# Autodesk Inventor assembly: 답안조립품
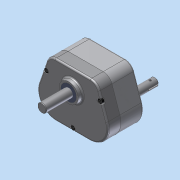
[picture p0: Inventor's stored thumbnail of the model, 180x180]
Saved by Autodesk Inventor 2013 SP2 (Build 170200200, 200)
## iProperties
Created: 2014-12
Part Number: 답안조립품
Document SubType Name: Assembly
Designer: dgall
Author: dgall
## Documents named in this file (14)
- C:\Documents and Settings\dgall\바탕 화면\441208V1037\답안조립품.iam
- C:\Documents and Settings\dgall\바탕 화면\441208V1037\본체.ipt
- C:\Documents and Settings\dgall\바탕 화면\441208V1037\커버.ipt
- C:\Documents and Settings\dgall\바탕 화면\441208V1037\메인축.ipt
- C:\Documents and Settings\dgall\바탕 화면\441208V1037\서브축.ipt
- C:\Documents and Settings\dgall\바탕 화면\441208V1037\메인기어.ipt
- C:\Documents and Settings\dgall\바탕 화면\441208V1037\서브기어.ipt
- C:\Documents and Settings\dgall\바탕 화면\441208V1037\멈춤링.ipt
- C:\Documents and Settings\dgall\바탕 화면\441208V1037\오일시일-D-15.ipt
- C:\Documents and Settings\dgall\바탕 화면\441208V1037\오일시일-D-17.ipt
- C:\Documents and Settings\dgall\바탕 화면\441208V1037\키5x5.ipt
- C:\Documents and Settings\dgall\바탕 화면\441208V1037\M 5 x 35.ipt
- C:\Documents and Settings\dgall\바탕 화면\441208V1037\베어링- 6203.ipt
- C:\Documents and Settings\dgall\바탕 화면\441208V1037\베어링- 6202.ipt
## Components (15 placed, 6 different names)
1. KS B 1336 17 x 1:1
2. KS B 1336 17 x 1:2
3. KS B 1336 17 x 1:3
4. KS B 2804 D D - 15 30 7:1
5. KS B 2804 D D - 15 30 7:2
6. KS B 2804 D D - 17 30 8:1
7. KS B 1003 - 미터 M 5 x 35:1
8. KS B 1003 - 미터 M 5 x 35:2
9. KS B 1003 - 미터 M 5 x 35:3
10. KS B 2023 6203 - 17 x 40 x 12:1
11. KS B 2023 6203 - 17 x 40 x 12:2
12. KS B 2023 6203 - 17 x 40 x 12:3
13. KS B 2023 6203 - 17 x 40 x 12:4
14. KS B 2023 6202 - 15 x 35 x 11:1
15. KS B 2023 6202 - 15 x 35 x 11:2
